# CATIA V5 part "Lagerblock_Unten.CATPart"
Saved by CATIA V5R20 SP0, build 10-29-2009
Part number: Lagerblock_Unten
Bounding box of the stored display mesh (mm): x 0 to 40, y -70 to 70, z 0 to 35
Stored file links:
  C:\Users\Andi\Desktop\Offene Projekte\Plasmacutter\Z-Achse\Lagerblock_Unten.CATPart
  C:\Program Files\Dassault Systemes\B20\win_b64\reffiles\standard\MetricThickPitch.txt
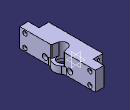
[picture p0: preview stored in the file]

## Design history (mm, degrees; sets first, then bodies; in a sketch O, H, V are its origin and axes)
Body1 (main body)
  Sketch1 on yz-plane, origin (0, 0, 0), H (0, 1, 0), V (0, 0, 1)
    line L1 (-50, 0) -> (-50, 35)
    line L2 (-50, 35) -> (50, 35)
    line L3 (50, 35) -> (50, 0)
    point P2 (50, 0)
    line L4 (50, 0) -> (-50, 0)
    distance L3 L1 = 100
    distance L2 L4 = 35
    vertical: L1 V, L3 V
    horizontal: L2 H, L4 H
    coincidence: P2 H
    symmetry: L1 L3 V
  Pad1: profile Sketch1, direction (1, 0, 0), length 40
  Sketch2 on face of Pad1 from Sketch1.L2, origin (0, 0, 35), H (1, 0, 0), V (0, 1, 0)
    arc A1 centre (25, 0) radius 9 from (22.6706, 8.6933) to (22.6706, -8.6933) ccw
    point P1 (25, 0)
    reference intersected line E1 through (0, 0) direction (0, 1) from yz-plane
    line L1 (22.6706, 8.6933) -> (32.5176, 11.3318)
    line L2 (22.6706, -8.6933) -> (32.5176, -11.3318)
    line L3 (40, 50) -> (40, -50)
    reference intersected line E2 (40, 50) -> (40, -50) from end face of Pad1
    line L4 (34, 13.2637) -> (34, 50)
    line L5 (34, -13.2637) -> (34, -50)
    point P5 (34, -11.729)
    line L6 (34, 50) -> (40, 50)
    line L7 (34, -50) -> (40, -50)
    reference intersected line E3 (0, 50) -> (40, 50) from face of Pad1 from Sketch1.L3
    reference intersected line E4 (40, -50) -> (0, -50) from face of Pad1 from Sketch1.L1
    arc A2 centre (32, 13.2637) radius 2 from (32.5176, 11.3318) to (34, 13.2637) ccw
    arc A3 centre (32, -13.2637) radius 2 from (32.5176, -11.3318) to (34, -13.2637) cw
    radius A1 = 9
    distance P1 E1 = 25
    distance V L4 = 34
    radius A2 = 2
    radius A3 = 2 {= Sketch2.radius(A2)}
    angle L1 L2 = 30
    coincidence: P1 H, L3 E2, P5 L4, E3 L6, L7 E4, L2 P5, L5 P5
    tangency: L1 A1, L2 A1, A2 L1, A2 L4, A3 L2, A3 L5
    vertical: L4 V, L5 V
    horizontal: L6 H, L7 H
    symmetry: L2 L1 H
  Pocket1: profile Sketch2, direction (0, 0, -1), length 22
  Sketch3 on face of Pad1 from Sketch1.L3, origin (8.2763, 50, 27.5196), H (1, 0, 0), V (0, 0, -1)
    point P1 (-0.2763, -1.4804)
    reference intersected line E1 (33.7237, -7.4804) -> (-8.2763, -7.4804) from face of Pad1 from Sketch1.L2
    reference intersected line E2 (-8.2763, -7.4804) -> (-8.2763, 27.5196) from start face of Pad1
    distance P1 E1 = 6
    distance E2 P1 = 8
  Hole1: placed by Sketch3, at (8, 50, 29) direction (0, -1, 0), diameter 4.134, depth 13, V-bottom angle 120, threaded "M5", thread diameter 5, thread depth 10, pitch 0.8
  Sketch4 on face of Pad1 from Sketch1.L1, origin (8.8422, -50, 27.569), H (1, 0, 0), V (0, 0, 1)
    point P1 (-0.8422, 1.431)
    reference projected point E1 (-0.8422, 1.431) from axis of face of Hole1
    coincidence: P1 E1
  Hole2: placed by Sketch4, at (8, -50, 29) direction (0, 1, 0), diameter 4.134, depth 15, V-bottom angle 120, threaded "M5", thread diameter 5, thread depth 12, pitch 0.8
  RectPattern1: of Hole1, Hole2, direction 1 instances 2, spacing 23, along face of Pad1 from Sketch1.L1 reversed
  Sketch5 on face of Pad1 from Sketch1.L4, origin (30.5677, -1.0037, 0), H (1, 0, 0), V (0, -1, 0)
    point P1 (-5.5677, -1.0037)
    reference projected point E1 (-5.5677, -1.0037) from axis of face of Pocket1 from Sketch2.A1
    coincidence: P1 E1
  Hole3: placed by Sketch5, at (25, 0, 0) direction (0, 0, 1), diameter 26, depth 8
  Sketch6 on end face of Pocket1, origin (0, 0, 13), H (1, 0, 0), V (0, 1, 0)
    circle A1 centre (25, 0) radius 9
    reference projected arc E1 centre (25, 0) radius 9 from (25, 9) to (25, -9) ccw from edge [face of Pad1 from Sketch1.L2 | face of Pocket1 from Sketch2.A1]
    coincidence: A1 E1
  Pocket2: profile Sketch6, direction (0, 0, 1), through (limit type 6)
  Sketch7 on face of Pad1 from Sketch1.L2, origin (0, 0, 35), H (1, 0, 0), V (0, 1, 0)
    arc A1 centre (25, 0) radius 15 from (36.4, -9.7488) to (36.4, 9.7488) ccw
    reference projected point E1 (25, 0) from axis of face of Pocket1 from Sketch2.A1
    reference intersected line E2 (40, 50) -> (40, -50) from end face of Pad1
    line L1 (34, 16.2481) -> (34, 50)
    line L2 (34, 50) -> (42, 50)
    line L3 (42, 50) -> (42, -50)
    line L4 (42, -50) -> (34, -50)
    line L5 (34, -50) -> (34, -16.2481)
    reference intersected line E3 (40, -50) -> (0, -50) from face of Pad1 from Sketch1.L1
    arc A2 centre (44, 16.2481) radius 10 from (36.4, 9.7488) to (34, 16.2481) cw
    arc A3 centre (44, -16.2481) radius 10 from (36.4, -9.7488) to (34, -16.2481) ccw
    reference intersected line E4 (0, 50) -> (40, 50) from face of Pad1 from Sketch1.L3
    reference intersected line E5 (40, 50) -> (40, -50) from end face of Pad1
    reference intersected line E6 (34, 9) -> (34, 50) from face of Pocket1 from Sketch2.L4
    radius A2 = 10
    radius A3 = 10 {= Sketch7.radius(A2)}
    distance E5 L3 = 2
    concentricity: E1 A1
    tangency: A1 E2, A2 A1, A2 L1, A3 A1, A3 L5
    vertical: L1 V, L3 V, L5 V
    horizontal: L2 H, L4 H
    coincidence: L1 L5, E3 L4, E4 L2, L1 E6
  Pocket3: profile Sketch7, direction (0, 0, -1), through (limit type 6)
  Sketch8 on face of Pocket3, origin (34, 28.8144, 11.8391), H (0, 1, 0), V (0, 0, 1)
    point P1 (-5.8144, -1.8391)
    reference intersected line E1 through (0, -11.8391) direction (-1, 0) from xy-plane
    reference intersected line E2 through (-28.8144, 0) direction (0, 1) from zx-plane
    distance E1 P1 = 10
    distance E2 P1 = 23
  Hole4: placed by Sketch8, at (34, 23, 10) direction (-1, 0, 0), diameter 5.5, through (limit type 6), counterbore diameter 10, counterbore depth 6
  RectPattern2: of Hole4, direction 1 instances 2, spacing 46, along end face of Pad1 reversed
  Sketch9 on face of Pad1 from Sketch1.L1, origin (0, -50, 0), H (1, 0, 0), V (0, 0, 1)
    line L1 (34, 35) -> (18, 35)
    line L2 (18, 35) -> (18, 0)
    line L3 (18, 0) -> (34, 0)
    line L4 (34, 0) -> (34, 35)
    point P3 (18, 0)
    reference intersected line E1 (0, 35) -> (40, 35) from face of Pad1 from Sketch1.L2
    reference intersected line E2 (34, 13) -> (34, 35) from face of Pocket1
    distance L2 L4 = 16
    horizontal: L1 H, L3 H
    vertical: L2 V, L4 V
    coincidence: P3 H, E1 L1, L4 E2
  Pad2: profile Sketch9, direction (0, -1, 0), length 20
  Mirror1: of Pad2, about zx-plane
  Sketch10 on face of Pad2, origin (34, -61.8017, 28.6383), H (0, 1, 0), V (0, 0, 1)
    point P1 (1.8017, 0.3617)
    reference intersected line E1 (-8.1983, -28.6383) -> (-8.1983, 6.3617) from end face of Pad2
    reference intersected line E2 (11.8017, 6.3617) -> (111.8017, 6.3617) from face of Pad2
    distance E1 P1 = 10
    distance E2 P1 = 6
  Hole5: placed by Sketch10, at (34, -60, 29) direction (-1, 0, 0), diameter 4.5, through (limit type 6), counterbore diameter 8, counterbore depth 4.5
  RectPattern3: of Hole5, direction 1 instances 2, spacing 120, along face of Pad2 reversed, direction 2 instances 2, spacing 23, along face of Pad2 reversed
